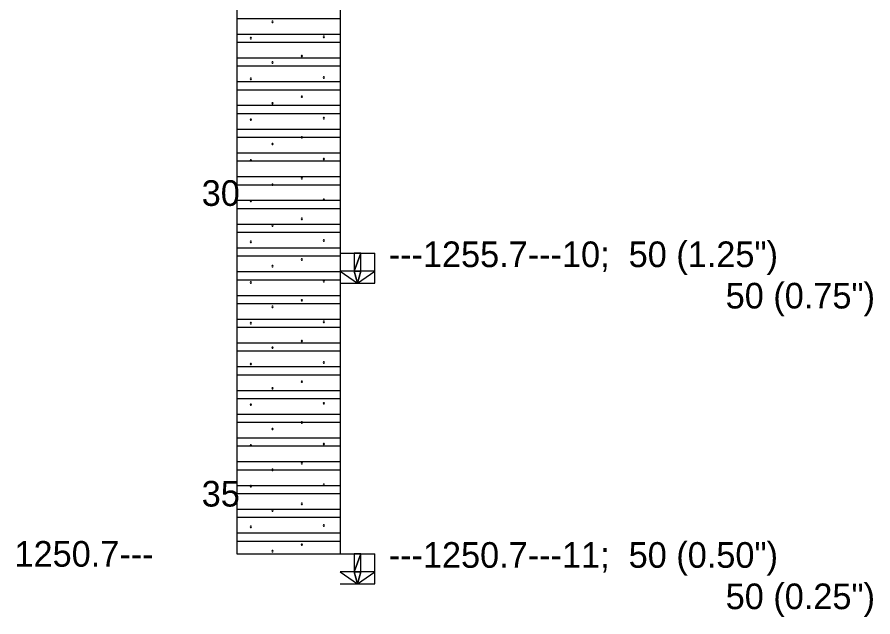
# Model space of a CAD drawing. Extents: x -6 to 173, y 24 to 64.
# Drawn here: x 100.634 to 104.774, y 38.755 to 41.654 of the extents above; entities that cross this region are included whole.
import ezdxf

# ---------------------------------------------------------------- set-up
doc = ezdxf.new("R2010")
doc.units = 0

msp = doc.modelspace()

# ---------------------------------------------------------------- linework, layer by layer
for points in [[(101.6976, 49.5245), (101.6976, 39.0593)], [(102.1976, 49.5245), (102.1976, 39.0593)], [(101.6976, 41.6477), (102.1976, 41.6477)], [(101.8727, 41.6312), (101.871, 41.6341), (101.8677, 41.6341), (101.8661, 41.6313), (101.8677, 41.6284), (101.871, 41.6284), (101.8727, 41.6312)], [(101.6976, 41.5722), (102.1976, 41.5722)], [(101.6976, 41.5329), (102.1976, 41.5329)], [(101.768, 41.5523), (101.7664, 41.5551), (101.7631, 41.5551), (101.7614, 41.5523), (101.7631, 41.5494), (101.7664, 41.5494), (101.768, 41.5523)], [(102.1208, 41.5588), (102.1191, 41.5617), (102.1158, 41.5617), (102.1142, 41.5588), (102.1158, 41.556), (102.1191, 41.556), (102.1208, 41.5588)], [(101.6976, 41.4574), (102.1976, 41.4574)], [(102.0152, 41.4663), (102.0136, 41.4691), (102.0103, 41.4691), (102.0087, 41.4663), (102.0103, 41.4635), (102.0136, 41.4635), (102.0152, 41.4663)], [(101.6976, 41.418), (102.1976, 41.418)], [(101.8727, 41.4344), (101.871, 41.4373), (101.8677, 41.4373), (101.8661, 41.4344), (101.8677, 41.4316), (101.871, 41.4316), (101.8727, 41.4344)], [(102.1208, 41.3619), (102.1191, 41.3648), (102.1158, 41.3648), (102.1142, 41.3619), (102.1158, 41.3591), (102.1191, 41.3591), (102.1208, 41.3619)], [(101.6976, 41.3426), (102.1976, 41.3426)], [(101.768, 41.3554), (101.7664, 41.3583), (101.7631, 41.3583), (101.7614, 41.3554), (101.7631, 41.3526), (101.7664, 41.3526), (101.768, 41.3554)], [(101.6976, 41.3032), (102.1976, 41.3032)], [(101.8727, 41.2375), (101.871, 41.2404), (101.8677, 41.2404), (101.8661, 41.2376), (101.8677, 41.2347), (101.871, 41.2347), (101.8727, 41.2375)], [(102.0152, 41.2694), (102.0136, 41.2722), (102.0103, 41.2722), (102.0087, 41.2694), (102.0103, 41.2666), (102.0136, 41.2666), (102.0152, 41.2694)], [(101.6976, 41.2278), (102.1976, 41.2278)], [(101.6976, 41.1884), (102.1976, 41.1884)], [(101.768, 41.1586), (101.7664, 41.1614), (101.7631, 41.1614), (101.7614, 41.1586), (101.7631, 41.1557), (101.7664, 41.1557), (101.768, 41.1586)], [(102.1208, 41.1651), (102.1191, 41.168), (102.1158, 41.168), (102.1142, 41.1651), (102.1158, 41.1623), (102.1191, 41.1623), (102.1208, 41.1651)], [(101.6976, 41.1129), (102.1976, 41.1129)], [(101.6976, 41.0736), (102.1976, 41.0736)], [(102.0152, 41.0726), (102.0136, 41.0754), (102.0103, 41.0754), (102.0087, 41.0726), (102.0103, 41.0697), (102.0136, 41.0697), (102.0152, 41.0726)], [(101.8727, 41.0407), (101.871, 41.0436), (101.8677, 41.0436), (101.8661, 41.0407), (101.8677, 41.0379), (101.871, 41.0379), (101.8727, 41.0407)], [(101.6976, 40.9981), (102.1976, 40.9981)], [(101.6976, 40.9587), (102.1976, 40.9587)], [(101.768, 40.9617), (101.7664, 40.9646), (101.7631, 40.9646), (101.7614, 40.9617), (101.7631, 40.9589), (101.7664, 40.9589), (101.768, 40.9617)], [(102.1208, 40.9682), (102.1191, 40.9711), (102.1158, 40.9711), (102.1142, 40.9682), (102.1158, 40.9654), (102.1191, 40.9654), (102.1208, 40.9682)], [(101.6976, 40.8833), (102.1976, 40.8833)], [(102.0152, 40.8757), (102.0136, 40.8785), (102.0103, 40.8785), (102.0087, 40.8757), (102.0103, 40.8729), (102.0136, 40.8729), (102.0152, 40.8757)], [(101.6976, 40.8439), (102.1976, 40.8439)], [(101.8727, 40.8438), (101.871, 40.8467), (101.8677, 40.8467), (101.8661, 40.8439), (101.8677, 40.841), (101.871, 40.841), (101.8727, 40.8438)], [(101.6976, 40.7684), (102.1976, 40.7684)], [(101.768, 40.7649), (101.7664, 40.7677), (101.7631, 40.7677), (101.7614, 40.7649), (101.7631, 40.762), (101.7664, 40.762), (101.768, 40.7649)], [(102.1208, 40.7714), (102.1191, 40.7743), (102.1158, 40.7743), (102.1142, 40.7714), (102.1158, 40.7686), (102.1191, 40.7686), (102.1208, 40.7714)], [(101.6976, 40.7291), (102.1976, 40.7291)], [(102.0152, 40.6789), (102.0136, 40.6817), (102.0103, 40.6817), (102.0087, 40.6789), (102.0103, 40.676), (102.0136, 40.676), (102.0152, 40.6789)], [(101.6976, 40.6536), (102.1976, 40.6536)], [(101.8727, 40.647), (101.871, 40.6499), (101.8677, 40.6499), (101.8661, 40.647), (101.8677, 40.6442), (101.871, 40.6442), (101.8727, 40.647)], [(101.6976, 40.6142), (102.1976, 40.6142)], [(102.1208, 40.5745), (102.1191, 40.5774), (102.1158, 40.5774), (102.1142, 40.5745), (102.1158, 40.5717), (102.1191, 40.5717), (102.1208, 40.5745)], [(101.6976, 40.5388), (102.1976, 40.5388)], [(101.768, 40.568), (101.7664, 40.5709), (101.7631, 40.5709), (101.7614, 40.568), (101.7631, 40.5652), (101.7664, 40.5652), (101.768, 40.568)], [(101.6976, 40.4994), (102.1976, 40.4994)], [(102.1976, 40.5128), (102.3643, 40.5128)], [(102.3643, 40.3675), (102.3643, 40.5128)], [(101.8727, 40.4501), (101.871, 40.453), (101.8677, 40.453), (101.8661, 40.4502), (101.8677, 40.4473), (101.871, 40.4473), (101.8727, 40.4501)], [(102.0152, 40.482), (102.0136, 40.4848), (102.0103, 40.4848), (102.0087, 40.482), (102.0103, 40.4792), (102.0136, 40.4792), (102.0152, 40.482)], [(101.6976, 40.4239), (102.1976, 40.4239)], [(101.6976, 40.3846), (102.1976, 40.3846)], [(101.768, 40.3712), (101.7664, 40.374), (101.7631, 40.374), (101.7614, 40.3712), (101.7631, 40.3683), (101.7664, 40.3683), (101.768, 40.3712)], [(102.1208, 40.3777), (102.1191, 40.3806), (102.1158, 40.3806), (102.1142, 40.3777), (102.1158, 40.3749), (102.1191, 40.3749), (102.1208, 40.3777)], [(102.1976, 40.3675), (102.3643, 40.3675)], [(101.6976, 40.3091), (102.1976, 40.3091)], [(102.0152, 40.2852), (102.0136, 40.288), (102.0103, 40.288), (102.0087, 40.2852), (102.0103, 40.2823), (102.0136, 40.2823), (102.0152, 40.2852)], [(101.6976, 40.2697), (102.1976, 40.2697)], [(101.8727, 40.2533), (101.871, 40.2562), (101.8677, 40.2562), (101.8661, 40.2533), (101.8677, 40.2505), (101.871, 40.2505), (101.8727, 40.2533)], [(101.6976, 40.1943), (102.1976, 40.1943)], [(101.768, 40.1743), (101.7664, 40.1772), (101.7631, 40.1772), (101.7614, 40.1743), (101.7631, 40.1715), (101.7664, 40.1715), (101.768, 40.1743)], [(102.1208, 40.1808), (102.1191, 40.1837), (102.1158, 40.1837), (102.1142, 40.1808), (102.1158, 40.178), (102.1191, 40.178), (102.1208, 40.1808)], [(101.6976, 40.1549), (102.1976, 40.1549)], [(101.6976, 40.0795), (102.1976, 40.0795)], [(102.0152, 40.0883), (102.0136, 40.0911), (102.0103, 40.0911), (102.0087, 40.0883), (102.0103, 40.0855), (102.0136, 40.0855), (102.0152, 40.0883)], [(101.6976, 40.0401), (102.1976, 40.0401)], [(101.8727, 40.0564), (101.871, 40.0593), (101.8677, 40.0593), (101.8661, 40.0565), (101.8677, 40.0536), (101.871, 40.0536), (101.8727, 40.0564)], [(101.6976, 39.9646), (102.1976, 39.9646)], [(101.768, 39.9775), (101.7664, 39.9803), (101.7631, 39.9803), (101.7614, 39.9775), (101.7631, 39.9746), (101.7664, 39.9746), (101.768, 39.9775)], [(102.1208, 39.984), (102.1191, 39.9869), (102.1158, 39.9869), (102.1142, 39.984), (102.1158, 39.9812), (102.1191, 39.9812), (102.1208, 39.984)], [(101.6976, 39.9253), (102.1976, 39.9253)], [(102.0152, 39.8915), (102.0136, 39.8943), (102.0103, 39.8943), (102.0087, 39.8915), (102.0103, 39.8886), (102.0136, 39.8886), (102.0152, 39.8915)], [(101.6976, 39.8498), (102.1976, 39.8498)], [(101.8727, 39.8596), (101.871, 39.8625), (101.8677, 39.8625), (101.8661, 39.8596), (101.8677, 39.8568), (101.871, 39.8568), (101.8727, 39.8596)], [(101.6976, 39.8104), (102.1976, 39.8104)], [(102.1208, 39.7871), (102.1191, 39.79), (102.1158, 39.79), (102.1142, 39.7871), (102.1158, 39.7843), (102.1191, 39.7843), (102.1208, 39.7871)], [(101.768, 39.7806), (101.7664, 39.7835), (101.7631, 39.7835), (101.7614, 39.7806), (101.7631, 39.7778), (101.7664, 39.7778), (101.768, 39.7806)], [(101.6976, 39.735), (102.1976, 39.735)], [(101.6976, 39.6956), (102.1976, 39.6956)], [(101.8727, 39.6627), (101.871, 39.6656), (101.8677, 39.6656), (101.8661, 39.6628), (101.8677, 39.6599), (101.871, 39.6599), (101.8727, 39.6627)], [(102.0152, 39.6946), (102.0136, 39.6974), (102.0103, 39.6974), (102.0087, 39.6946), (102.0103, 39.6918), (102.0136, 39.6918), (102.0152, 39.6946)], [(101.6976, 39.6201), (102.1976, 39.6201)], [(101.6976, 39.5808), (102.1976, 39.5808)], [(101.768, 39.5838), (101.7664, 39.5866), (101.7631, 39.5866), (101.7614, 39.5838), (101.7631, 39.5809), (101.7664, 39.5809), (101.768, 39.5838)], [(102.1208, 39.5903), (102.1191, 39.5932), (102.1158, 39.5932), (102.1142, 39.5903), (102.1158, 39.5875), (102.1191, 39.5875), (102.1208, 39.5903)], [(101.6976, 39.5053), (102.1976, 39.5053)], [(102.0152, 39.4978), (102.0136, 39.5006), (102.0103, 39.5006), (102.0087, 39.4978), (102.0103, 39.4949), (102.0136, 39.4949), (102.0152, 39.4978)], [(101.6976, 39.4659), (102.1976, 39.4659)], [(101.8727, 39.4659), (101.871, 39.4688), (101.8677, 39.4688), (101.8661, 39.4659), (101.8677, 39.4631), (101.871, 39.4631), (101.8727, 39.4659)], [(101.6976, 39.3905), (102.1976, 39.3905)], [(101.768, 39.3869), (101.7664, 39.3898), (101.7631, 39.3898), (101.7614, 39.3869), (101.7631, 39.3841), (101.7664, 39.3841), (101.768, 39.3869)], [(102.1208, 39.3934), (102.1191, 39.3963), (102.1158, 39.3963), (102.1142, 39.3934), (102.1158, 39.3906), (102.1191, 39.3906), (102.1208, 39.3934)], [(101.6976, 39.3511), (102.1976, 39.3511)], [(102.0152, 39.3009), (102.0136, 39.3037), (102.0103, 39.3037), (102.0087, 39.3009), (102.0103, 39.2981), (102.0136, 39.2981), (102.0152, 39.3009)], [(101.6976, 39.2757), (102.1976, 39.2757)], [(101.8727, 39.269), (101.871, 39.2719), (101.8677, 39.2719), (101.8661, 39.2691), (101.8677, 39.2662), (101.871, 39.2662), (101.8727, 39.269)], [(101.6976, 39.2363), (102.1976, 39.2363)], [(101.768, 39.1901), (101.7664, 39.1929), (101.7631, 39.1929), (101.7614, 39.1901), (101.7631, 39.1872), (101.7664, 39.1872), (101.768, 39.1901)], [(102.1208, 39.1966), (102.1191, 39.1995), (102.1158, 39.1995), (102.1142, 39.1966), (102.1158, 39.1938), (102.1191, 39.1938), (102.1208, 39.1966)], [(101.6976, 39.1608), (102.1976, 39.1608)], [(101.6976, 39.1215), (102.1976, 39.1215)], [(102.0152, 39.1041), (102.0136, 39.1069), (102.0103, 39.1069), (102.0087, 39.1041), (102.0103, 39.1012), (102.0136, 39.1012), (102.0152, 39.1041)], [(101.6976, 39.0593), (102.1976, 39.0593)], [(101.8727, 39.0722), (101.871, 39.0751), (101.8677, 39.0751), (101.8661, 39.0722), (101.8677, 39.0694), (101.871, 39.0694), (101.8727, 39.0722)], [(102.1976, 39.0593), (102.3643, 39.0593)], [(102.3643, 38.914), (102.3643, 39.0593)], [(102.1976, 38.914), (102.3643, 38.914)]]:
    msp.add_lwpolyline(points)
for points in [[(102.2643, 40.4256), (102.2976, 40.4256), (102.2976, 40.5128), (102.2643, 40.4256)], [(102.2643, 40.4256), (102.2976, 40.5128), (102.2643, 40.5128), (102.2643, 40.4256)], [(102.2643, 40.4256), (102.1976, 40.4256), (102.2809, 40.3675), (102.2643, 40.4256)], [(102.2643, 40.4256), (102.2809, 40.3675), (102.2976, 40.4256), (102.2643, 40.4256)], [(102.2809, 40.3675), (102.3643, 40.4256), (102.2976, 40.4256), (102.2809, 40.3675)], [(102.2643, 38.9721), (102.2976, 38.9721), (102.2976, 39.0593), (102.2643, 38.9721)], [(102.2643, 38.9721), (102.2976, 39.0593), (102.2643, 39.0593), (102.2643, 38.9721)], [(102.2643, 38.9721), (102.1976, 38.9721), (102.2809, 38.914), (102.2643, 38.9721)], [(102.2643, 38.9721), (102.2809, 38.914), (102.2976, 38.9721), (102.2643, 38.9721)], [(102.2809, 38.914), (102.3643, 38.9721), (102.2976, 38.9721), (102.2809, 38.914)]]:
    msp.add_lwpolyline(points, close=True)

# ---------------------------------------------------------------- texts
for s, p in [('30', (101.5272, 40.7415)), ('---1255.7---10;  50 (1.25")', (102.4317, 40.4455)), ('50 (0.75")', (104.0621, 40.2455)), ('35', (101.5272, 39.288)), ('1250.7---', (100.6215, 38.9973)), ('---1250.7---11;  50 (0.50")', (102.4317, 38.992)), ('50 (0.25")', (104.0621, 38.792))]:
    msp.add_text(s, height=0.124).set_placement(p)

doc.saveas('drawing.dxf')
